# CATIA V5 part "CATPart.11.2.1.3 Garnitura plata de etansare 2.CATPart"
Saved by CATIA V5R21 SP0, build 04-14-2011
Part number: Garnitura plata de etanşare.1.2
Bounding box of the stored display mesh (mm): x -20 to 20, y -20 to 20, z 0 to 3
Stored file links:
  C:\Users\MIRCEA\Desktop\MOM\Mogan\model\CATPart.11.2.1.3 Garnitura plata de etansare 2.CATPart
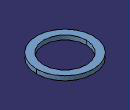
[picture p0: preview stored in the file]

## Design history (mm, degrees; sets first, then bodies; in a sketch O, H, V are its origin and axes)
Parameters
  Di = 30 mm
  De = 40 mm
  h = 3 mm
AxisSystem1: origin (0, 0, 0), X (1, 0, 0), Y (0, 1, 0), Z (0, 0, 1)
Body1 (main body)
  Sketch1 on xy-plane, origin (0, 0, 0), H (1, 0, 0), V (0, 1, 0)
    circle A1 centre (0, 0) radius 15
    circle A2 centre (0, 0) radius 20
    radius A1 = 15 {= Di/2}
    radius A2 = 20 {= De/2}
  Pad1: profile Sketch1, direction (0, 0, 1), length 3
